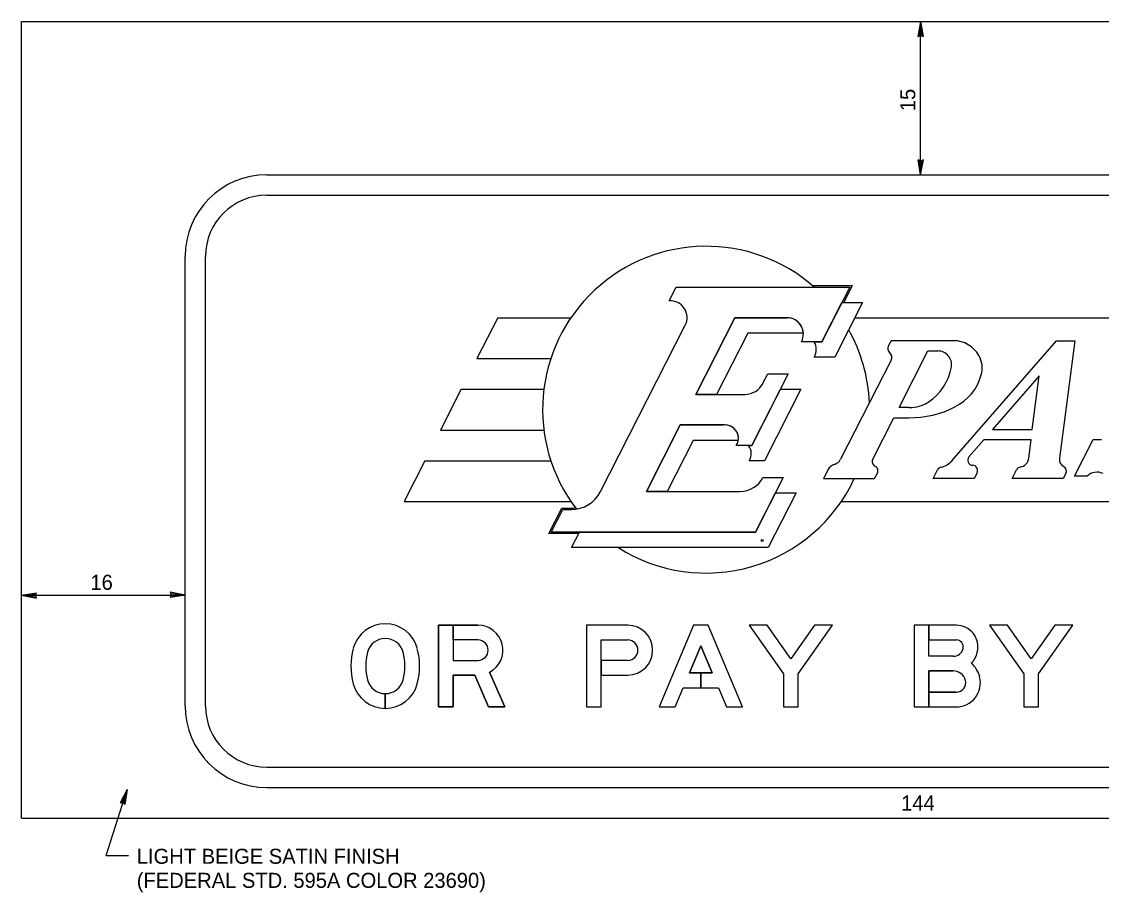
# Model space of a CAD drawing. Extents: x 60714 to 61340, y 9359 to 9750.
# Drawn here: x 60766.6 to 60967.4, y 9588.1 to 9750.1 of the extents above; entities that cross this region are included whole.
import ezdxf

# ---------------------------------------------------------------- set-up
doc = ezdxf.new("R2010")
doc.units = 0
for name, color, linetype in [('1', 7, 'Continuous'), ('2', 7, 'Continuous'), ('52', 7, 'Continuous'), ('GSBWFill', 7, 'Continuous'), ('SignPanel', 7, 'Continuous')]:
    doc.layers.add(name, color=color, linetype=linetype)

msp = doc.modelspace()

# ---------------------------------------------------------------- linework, layer by layer
at = {"layer": '1'}
for p, q in [((60933.77, 9721.63), (60933.77, 9750.13)), ((60766.57, 9643.41), (60796.97, 9643.41)), ((60782.32, 9595), (60786.23, 9607.24)), ((60782.32, 9595), (60786.43, 9594.97))]:
    msp.add_line(p, q, dxfattribs=at)
msp.add_circle((60904.31, 9653.58), 0.19, dxfattribs=at)
at = {"layer": '2'}
for p, q in [((60766.57, 9601.93), (60766.57, 9750.13)), ((60766.57, 9750.13), (61100.97, 9750.13)), ((60766.57, 9601.93), (61100.97, 9601.93))]:
    msp.add_line(p, q, dxfattribs=at)
at = {"layer": '52'}
for p, q in [((60933.77, 9750.13), (60933.23, 9747.37)), ((60933.77, 9750.13), (60933.49, 9747.48)), ((60933.77, 9750.13), (60934.21, 9747.35)), ((60933.77, 9750.13), (60933.96, 9747.47)), ((60933.23, 9747.37), (60933.73, 9747.57)), ((60933.73, 9747.57), (60934.21, 9747.35)), ((60933.77, 9721.63), (60933.33, 9724.41)), ((60933.81, 9724.19), (60933.33, 9724.41)), ((60933.77, 9721.63), (60933.58, 9724.29)), ((60933.77, 9721.63), (60934.31, 9724.39)), ((60933.77, 9721.63), (60934.05, 9724.28)), ((60934.31, 9724.39), (60933.81, 9724.19)), ((60766.57, 9643.41), (60769.35, 9643.85)), ((60766.57, 9643.41), (60769.23, 9643.6)), ((60766.57, 9643.41), (60769.33, 9642.88)), ((60766.57, 9643.41), (60769.22, 9643.13)), ((60769.13, 9643.37), (60769.35, 9643.85)), ((60769.33, 9642.88), (60769.13, 9643.37)), ((60794.41, 9643.46), (60794.19, 9642.97)), ((60796.97, 9643.41), (60794.19, 9642.97)), ((60796.97, 9643.41), (60794.21, 9643.95)), ((60794.21, 9643.95), (60794.41, 9643.46)), ((60796.97, 9643.41), (60794.31, 9643.69)), ((60796.97, 9643.41), (60794.31, 9643.23)), ((60786.23, 9607.24), (60784.88, 9604.78)), ((60786.23, 9607.24), (60785.15, 9604.8)), ((60786.23, 9607.24), (60785.59, 9604.65)), ((60786.23, 9607.24), (60785.8, 9604.46)), ((60784.88, 9604.78), (60785.41, 9604.82)), ((60785.41, 9604.82), (60785.8, 9604.46))]:
    msp.add_line(p, q, dxfattribs=at)
at = {"layer": 'GSBWFill'}
for p, q in [((60874.35, 9635.09), (60879.29, 9635.09)), ((60874.35, 9635.09), (60879.29, 9635.09)), ((60874.35, 9635.09), (60879.29, 9635.09)), ((60874.35, 9628.56), (60879.29, 9628.56)), ((60834.21, 9622.36), (60834.21, 9625.1)), ((60834.21, 9625.1), (60834.21, 9622.36)), ((60834.21, 9622.36), (60834.21, 9625.1)), ((60834.21, 9625.1), (60834.21, 9622.36)), ((60932.58, 9622.63), (60940.4, 9622.63))]:
    msp.add_line(p, q, dxfattribs=at)
for points in [[(60851.44, 9637.83), (60844.09, 9637.83), (60844.09, 9622.63), (60846.83, 9622.63), (60846.83, 9628.56), (60850.86, 9628.56), (60853.42, 9622.63), (60856.41, 9622.63), (60853.61, 9629.09)], [(60853.61, 9629.09), (60856.41, 9622.63), (60853.42, 9622.63), (60850.86, 9628.56), (60846.83, 9628.56), (60846.83, 9622.63), (60844.09, 9622.63), (60844.09, 9637.83), (60846.83, 9637.83), (60846.83, 9631.29), (60851.44, 9631.29)], [(60853.61, 9629.09), (60856.41, 9622.63), (60853.42, 9622.63), (60850.86, 9628.56), (60846.83, 9628.56), (60846.83, 9622.63), (60844.09, 9622.63), (60844.09, 9637.83), (60846.83, 9637.83), (60846.83, 9631.29), (60851.44, 9631.29)], [(60846.83, 9635.09), (60846.83, 9637.83), (60851.44, 9637.83)], [(60846.83, 9635.09), (60846.83, 9637.83), (60851.44, 9637.83)], [(60879.29, 9637.83), (60871.61, 9637.83), (60871.61, 9622.63), (60874.35, 9622.63), (60874.35, 9628.56)], [(60879.29, 9637.83), (60871.61, 9637.83), (60871.61, 9622.63), (60874.35, 9622.63), (60874.35, 9635.09)], [(60879.29, 9637.83), (60871.61, 9637.83), (60871.61, 9622.63), (60874.35, 9622.63), (60874.35, 9635.09)], [(60940.4, 9637.83), (60932.58, 9637.83), (60932.58, 9622.63)], [(60939.82, 9632.05), (60935.31, 9632.05), (60935.31, 9637.83), (60932.58, 9637.83), (60932.58, 9622.63), (60935.31, 9622.63)], [(60939.82, 9632.05), (60935.31, 9632.05), (60935.31, 9637.83), (60932.58, 9637.83), (60932.58, 9622.63), (60935.31, 9622.63)], [(60940.4, 9637.83), (60935.31, 9637.83), (60935.31, 9635.09), (60940.4, 9635.09)], [(60940.4, 9637.83), (60935.31, 9637.83), (60935.31, 9635.09), (60940.4, 9635.09)], [(60851.44, 9635.09), (60846.83, 9635.09), (60846.83, 9631.29), (60851.44, 9631.29)], [(60851.44, 9635.09), (60846.83, 9635.09)], [(60851.44, 9635.09), (60846.83, 9635.09)], [(60879.29, 9631.29), (60874.35, 9631.29), (60874.35, 9635.09)], [(60939.82, 9632.05), (60935.31, 9632.05), (60935.31, 9635.09), (60940.4, 9635.09)], [(60879.29, 9631.29), (60874.35, 9631.29), (60874.35, 9628.56), (60879.29, 9628.56)], [(60879.29, 9631.29), (60874.35, 9631.29), (60874.35, 9628.56), (60879.29, 9628.56)], [(60939.82, 9629.32), (60935.31, 9629.32), (60935.31, 9625.36), (60940.4, 9625.36)], [(60935.31, 9622.63), (60935.31, 9629.32), (60939.82, 9629.32)], [(60935.31, 9622.63), (60935.31, 9629.32), (60939.82, 9629.32)], [(60940.4, 9625.36), (60935.31, 9625.36), (60935.31, 9622.63), (60940.4, 9622.63)], [(60940.4, 9625.36), (60935.31, 9625.36), (60935.31, 9622.63), (60940.4, 9622.63)]]:
    msp.add_lwpolyline(points, dxfattribs=at)
for points in [[(60889.61, 9626.2), (60896.18, 9626.2), (60897.68, 9622.63), (60900.65, 9622.63), (60894.26, 9637.83), (60891.53, 9637.83), (60885.14, 9622.63), (60888.11, 9622.63)], [(60895.03, 9628.94), (60892.89, 9628.94), (60892.89, 9626.2), (60896.18, 9626.2), (60897.68, 9622.63), (60900.65, 9622.63), (60894.26, 9637.83), (60891.53, 9637.83), (60885.14, 9622.63), (60888.11, 9622.63), (60889.61, 9626.2), (60892.89, 9626.2), (60892.89, 9628.94), (60890.76, 9628.94), (60892.89, 9634.02)], [(60895.03, 9628.94), (60892.89, 9628.94), (60892.89, 9626.2), (60896.18, 9626.2), (60897.68, 9622.63), (60900.65, 9622.63), (60894.26, 9637.83), (60891.53, 9637.83), (60885.14, 9622.63), (60888.11, 9622.63), (60889.61, 9626.2), (60892.89, 9626.2), (60892.89, 9628.94), (60890.76, 9628.94), (60892.89, 9634.02)], [(60910.99, 9628.78), (60917.37, 9637.83), (60914.02, 9637.83), (60909.62, 9631.59), (60905.21, 9637.83), (60901.86, 9637.83), (60908.25, 9628.78), (60908.25, 9622.63), (60910.99, 9622.63)], [(60910.99, 9628.78), (60917.37, 9637.83), (60914.02, 9637.83), (60909.62, 9631.59), (60905.21, 9637.83), (60901.86, 9637.83), (60908.25, 9628.78), (60908.25, 9622.63), (60910.99, 9622.63)], [(60910.99, 9628.78), (60917.37, 9637.83), (60914.02, 9637.83), (60909.62, 9631.59), (60905.21, 9637.83), (60901.86, 9637.83), (60908.25, 9628.78), (60908.25, 9622.63), (60910.99, 9622.63)], [(60955.68, 9628.78), (60962.07, 9637.83), (60958.72, 9637.83), (60954.32, 9631.59), (60949.91, 9637.83), (60946.56, 9637.83), (60952.95, 9628.78), (60952.95, 9622.63), (60955.68, 9622.63)], [(60955.68, 9628.78), (60962.07, 9637.83), (60958.72, 9637.83), (60954.32, 9631.59), (60949.91, 9637.83), (60946.56, 9637.83), (60952.95, 9628.78), (60952.95, 9622.63), (60955.68, 9622.63)], [(60955.68, 9628.78), (60962.07, 9637.83), (60958.72, 9637.83), (60954.32, 9631.59), (60949.91, 9637.83), (60946.56, 9637.83), (60952.95, 9628.78), (60952.95, 9622.63), (60955.68, 9622.63)], [(60895.03, 9628.94), (60892.89, 9634.02), (60890.76, 9628.94)]]:
    msp.add_lwpolyline(points, close=True, dxfattribs=at)
for centre, radius, start, end in [((60834.21, 9631.94), 6.16, 14.9618, 165.0382), ((60834.21, 9631.94), 6.16, 14.9618, 165.0382), ((60834.21, 9631.94), 6.16, 14.9618, 165.0382), ((60851.44, 9633.19), 4.64, 297.837, 90), ((60851.44, 9633.19), 4.64, 297.837, 90), ((60851.44, 9633.19), 4.64, 297.837, 90), ((60940.4, 9633.8), 4.03, 345.5225, 90), ((60940.4, 9633.8), 4.03, 345.5225, 90), ((60940.4, 9633.8), 4.03, 345.5225, 90), ((60834.21, 9631.94), 3.42, 14.9618, 165.0382), ((60834.21, 9631.94), 3.42, 14.9618, 165.0382), ((60834.21, 9631.94), 3.42, 14.9618, 165.0382), ((60840.59, 9630.23), 12.77, 165.0382, 194.9618), ((60840.59, 9630.23), 12.77, 165.0382, 194.9618), ((60840.59, 9630.23), 12.77, 165.0382, 194.9618), ((60827.82, 9630.23), 12.77, 345.0382, 14.9618), ((60827.82, 9630.23), 12.77, 345.0382, 14.9618), ((60827.82, 9630.23), 12.77, 345.0382, 14.9618), ((60851.44, 9633.19), 1.9, 270, 90), ((60851.44, 9633.19), 1.9, 270, 90), ((60851.44, 9633.19), 1.9, 270, 90), ((60939.82, 9633.95), 1.9, 270, 345.5225), ((60939.82, 9633.95), 1.9, 270, 345.5225), ((60939.82, 9633.95), 1.9, 270, 345.5225), ((60940.4, 9633.8), 1.29, 345.5225, 90), ((60940.4, 9633.8), 1.29, 345.5225, 90), ((60940.4, 9633.8), 1.29, 345.5225, 90), ((60840.59, 9630.23), 10.03, 165.0382, 194.9618), ((60840.59, 9630.23), 10.03, 165.0382, 194.9618), ((60840.59, 9630.23), 10.03, 165.0382, 194.9618), ((60827.82, 9630.23), 10.03, 345.0382, 14.9618), ((60827.82, 9630.23), 10.03, 345.0382, 14.9618), ((60827.82, 9630.23), 10.03, 345.0382, 14.9618), ((60939.82, 9633.95), 4.64, 316.7114, 345.5225), ((60939.82, 9633.95), 4.64, 316.7114, 345.5225), ((60939.82, 9633.95), 4.64, 316.7114, 345.5225), ((60939.82, 9626.96), 2.36, 14.4775, 90), ((60939.82, 9626.96), 2.36, 14.4775, 90), ((60939.82, 9626.96), 2.36, 14.4775, 90), ((60939.82, 9626.96), 5.09, 14.4775, 48.4921), ((60939.82, 9626.96), 5.09, 14.4775, 48.4921), ((60939.82, 9626.96), 5.09, 14.4775, 48.4921), ((60834.21, 9628.52), 3.42, 194.9618, 345.0382), ((60834.21, 9628.52), 3.42, 194.9618, 270), ((60834.21, 9628.52), 3.42, 194.9618, 270), ((60834.21, 9628.52), 3.42, 270.0127, 345.0382), ((60834.21, 9628.52), 3.42, 270.0127, 345.0382), ((60940.4, 9627.11), 4.49, 270, 14.4775), ((60940.4, 9627.11), 4.49, 270, 14.4775), ((60940.4, 9627.11), 4.49, 270, 14.4775), ((60940.4, 9627.11), 1.75, 270, 14.4775), ((60940.4, 9627.11), 1.75, 270, 14.4775), ((60940.4, 9627.11), 1.75, 270, 14.4775), ((60834.21, 9628.52), 6.16, 194.9618, 345.0382), ((60834.21, 9628.52), 6.16, 194.9618, 270), ((60834.21, 9628.52), 6.16, 194.9618, 270), ((60834.21, 9628.52), 6.16, 270.0071, 345.0382), ((60834.21, 9628.52), 6.16, 270.0071, 345.0382)]:
    msp.add_arc(centre, radius, start, end, dxfattribs=at)
for major_axis in [(0, 4.64), (0, 4.64), (0, 4.64), (0, 1.9), (0, 1.9), (0, 1.9)]:
    msp.add_ellipse((60879.29, 9633.19), major_axis=major_axis, ratio=0.999994, start_param=3.141593, end_param=6.283185, dxfattribs=at)
at = {"layer": 'SignPanel'}
for p, q in [((60812.17, 9721.63), (61055.37, 9721.63)), ((60812.17, 9717.83), (61055.37, 9717.83)), ((60796.97, 9622.83), (60796.97, 9706.43)), ((60800.77, 9622.83), (60800.77, 9706.43)), ((60886.99, 9698.18), (60888.29, 9700.73)), ((60888.29, 9700.73), (60920.59, 9700.73)), ((60913.65, 9701.02), (60921.05, 9701.02)), ((60920.59, 9700.73), (60915.42, 9690.57)), ((60921.05, 9701.02), (60919.46, 9697.88)), ((60915.41, 9690.56), (60919.14, 9697.88)), ((60915.41, 9690.56), (60919.14, 9697.88)), ((60922.98, 9697.88), (60917.8, 9687.72)), ((60922.98, 9697.88), (60917.8, 9687.72)), ((60919.14, 9697.88), (60922.98, 9697.88)), ((60919.14, 9697.88), (60922.98, 9697.88)), ((60855.11, 9695.03), (60851.24, 9687.43)), ((60855.11, 9695.03), (60868.73, 9695.03)), ((60874.23, 9662.68), (60890, 9693.63)), ((60899.24, 9695.03), (60891.98, 9680.78)), ((60891.98, 9680.78), (60899.24, 9695.03)), ((60891.98, 9680.78), (60899.24, 9695.03)), ((60908.92, 9695.03), (60899.24, 9695.03)), ((60899.24, 9695.03), (60908.92, 9695.03)), ((60899.24, 9695.03), (60908.92, 9695.03)), ((60921.52, 9695.03), (61029.91, 9695.03)), ((60901.62, 9692.18), (60895.81, 9680.78)), ((60901.62, 9692.18), (60895.81, 9680.78)), ((60911.96, 9692.18), (60901.62, 9692.18)), ((60911.96, 9692.18), (60901.62, 9692.18)), ((60915.42, 9690.57), (60911.61, 9690.57)), ((60914, 9690.56), (60915.41, 9690.56)), ((60914, 9690.56), (60915.41, 9690.56)), ((60928.26, 9690.76), (60927.74, 9689.74)), ((60939.89, 9690.76), (60928.26, 9690.76)), ((60939.6, 9668.44), (60959.01, 9690.76)), ((60959.01, 9690.76), (60962.43, 9690.76)), ((60962.43, 9690.76), (60959.58, 9668.89)), ((60917.8, 9687.72), (60914, 9687.72)), ((60917.8, 9687.72), (60914, 9687.72)), ((60929.75, 9678.31), (60935.13, 9688.86)), ((60935.13, 9688.86), (60936.96, 9688.86)), ((60851.24, 9687.43), (60864.99, 9687.43)), ((60928.29, 9687.16), (60918.88, 9668.7)), ((60909.13, 9684.58), (60902.36, 9671.28)), ((60904.45, 9682.86), (60905.33, 9684.58)), ((60905.33, 9684.58), (60909.13, 9684.58)), ((60955.82, 9684.2), (60947.15, 9674.22)), ((60954.53, 9674.22), (60955.82, 9684.2)), ((60848.34, 9681.73), (60844.47, 9674.13)), ((60848.34, 9681.73), (60863.71, 9681.73)), ((60902.36, 9671.28), (60907.68, 9681.73)), ((60902.36, 9671.28), (60907.68, 9681.73)), ((60911.52, 9681.73), (60904.74, 9668.43)), ((60911.52, 9681.73), (60904.74, 9668.43)), ((60907.68, 9681.73), (60911.52, 9681.73)), ((60907.68, 9681.73), (60911.52, 9681.73)), ((60891.98, 9680.78), (60901.07, 9680.78)), ((60895.81, 9680.78), (60891.98, 9680.78)), ((60895.81, 9680.78), (60891.98, 9680.78)), ((60931.63, 9678.31), (60929.75, 9678.31)), ((60924.85, 9668.7), (60928.78, 9676.41)), ((60928.78, 9676.41), (60931.63, 9676.41)), ((60844.47, 9674.13), (60863.71, 9674.13)), ((60889.07, 9675.08), (60882.78, 9662.73)), ((60882.78, 9662.73), (60889.07, 9675.08)), ((60882.78, 9662.73), (60889.07, 9675.08)), ((60897.41, 9675.08), (60889.07, 9675.08)), ((60889.07, 9675.08), (60897.05, 9675.06)), ((60889.07, 9675.08), (60897.05, 9675.06)), ((60947.15, 9674.22), (60954.53, 9674.22)), ((60891.46, 9672.22), (60886.62, 9662.73)), ((60891.46, 9672.22), (60886.62, 9662.73)), ((60899.85, 9672.2), (60891.46, 9672.22)), ((60899.85, 9672.2), (60891.46, 9672.22)), ((60945.5, 9672.32), (60942.75, 9669.16)), ((60954.33, 9672.32), (60945.5, 9672.32)), ((60953.88, 9668.89), (60954.33, 9672.32)), ((60962.41, 9665.58), (60965.86, 9672.35)), ((60965.86, 9672.35), (60967.39, 9672.35)), ((60902.36, 9671.28), (60899.49, 9671.28)), ((60901.76, 9671.28), (60902.36, 9671.28)), ((60901.76, 9671.28), (60902.36, 9671.28)), ((60841.57, 9668.43), (60837.7, 9660.83)), ((60841.57, 9668.43), (60864.99, 9668.43)), ((60904.74, 9668.43), (60901.89, 9668.43)), ((60904.74, 9668.43), (60901.89, 9668.43)), ((60916.57, 9666.78), (60915.72, 9665.1)), ((60925.22, 9665.1), (60925.74, 9666.12)), ((60936.11, 9665.1), (60936.93, 9666.73)), ((60944.27, 9666.2), (60943.71, 9665.1)), ((60950.77, 9665.1), (60951.61, 9666.76)), ((60960.77, 9666.08), (60960.27, 9665.1)), ((60964.72, 9665.58), (60962.41, 9665.58)), ((60908.23, 9665.29), (60903.06, 9655.13)), ((60904.43, 9665.29), (60908.23, 9665.29)), ((60915.72, 9665.1), (60925.22, 9665.1)), ((60943.71, 9665.1), (60936.11, 9665.1)), ((60960.27, 9665.1), (60950.77, 9665.1)), ((60882.78, 9662.73), (60900.22, 9662.73)), ((60886.62, 9662.73), (60882.78, 9662.73)), ((60886.62, 9662.73), (60882.78, 9662.73)), ((60903.06, 9655.13), (60906.78, 9662.44)), ((60903.06, 9655.13), (60906.78, 9662.44)), ((60910.62, 9662.44), (60905.44, 9652.28)), ((60910.62, 9662.44), (60905.44, 9652.28)), ((60906.78, 9662.44), (60910.62, 9662.44)), ((60906.78, 9662.44), (60910.62, 9662.44)), ((60837.7, 9660.83), (60868.73, 9660.83)), ((60864.65, 9654.88), (60867.06, 9659.61)), ((60867.06, 9659.61), (60868.81, 9659.61)), ((60919, 9660.83), (61012.48, 9660.83)), ((60865.06, 9655.13), (60867.21, 9659.36)), ((60867.21, 9659.36), (60868.81, 9659.36)), ((60870.18, 9654.88), (60864.65, 9654.88)), ((60903.06, 9655.13), (60865.06, 9655.13)), ((60868.86, 9652.28), (60870.31, 9655.13)), ((60868.86, 9652.28), (60870.31, 9655.13)), ((60870.31, 9655.13), (60903.06, 9655.13)), ((60870.31, 9655.13), (60903.06, 9655.13)), ((60905.44, 9652.28), (60868.86, 9652.28)), ((60905.44, 9652.28), (60868.86, 9652.28)), ((60812.17, 9611.43), (61055.37, 9611.43)), ((60812.17, 9607.63), (61055.37, 9607.63))]:
    msp.add_line(p, q, dxfattribs=at)
for centre, radius, start, end in [((60812.17, 9706.43), 15.2, 90, 180), ((60812.17, 9706.43), 11.4, 90, 180), ((60893.87, 9677.93), 30.4, 48.5904, 217.4727), ((60887.2, 9695.05), 3.14, 332.9998, 93.8045), ((60908.92, 9691.99), 3.04, 332.2089, 90), ((60908.92, 9691.99), 3.04, 3.5833, 90), ((60908.92, 9691.99), 3.04, 3.5833, 90), ((60893.87, 9677.93), 30.4, 2.4236, 29.2771), ((60911.31, 9689.14), 3.04, 332.2089, 27.9127), ((60911.31, 9689.14), 3.04, 332.2089, 27.9127), ((60928.59, 9689.31), 0.95, 152.9784, 231.1602), ((60939.89, 9685.34), 5.42, 29.4315, 90), ((60927.28, 9687.68), 1.14, 333.0027, 51.1602), ((60936.95, 9686.29), 2.57, 351.076, 90), ((60940.47, 9685.66), 4.75, 344.7074, 29.4315), ((60930.1, 9687.36), 9.5, 302.4206, 351.076), ((60935.89, 9686.92), 9.5, 296.6432, 344.7074), ((60901.07, 9684.58), 3.8, 270, 332.9883), ((60931.63, 9684.96), 6.65, 270, 302.4206), ((60931.63, 9695.41), 19, 270, 296.6432), ((60897.41, 9672.61), 2.47, 350.3502, 98.3344), ((60897.41, 9672.61), 2.47, 350.3502, 98.3344), ((60897.41, 9672.61), 2.47, 327.421, 90), ((60899.81, 9669.76), 2.47, 327.421, 37.9799), ((60899.81, 9669.76), 2.47, 327.421, 37.9799), ((60918.27, 9665.92), 1.9, 106.4317, 152.9742), ((60917.19, 9669.56), 1.9, 286.4317, 332.9959), ((60925.7, 9668.27), 0.95, 152.9884, 244.7832), ((60924.89, 9666.55), 0.95, 333.0239, 64.7832), ((60936.74, 9670.93), 3.8, 282.7162, 318.9966), ((60943.47, 9668.53), 0.95, 138.9824, 268.6869), ((60943.42, 9666.63), 0.95, 332.9784, 88.6869), ((60952, 9669.13), 1.9, 279.2397, 352.5632), ((60961.09, 9668.69), 1.52, 172.5884, 241.8673), ((60937.78, 9666.3), 0.95, 102.7162, 153.0239), ((60952.46, 9666.32), 0.95, 99.2397, 153.0239), ((60959.92, 9666.51), 0.95, 332.9784, 61.8673), ((60966.54, 9663.64), 2.66, 64.3795, 133.1892), ((60893.87, 9677.93), 30.4, 237.5383, 335.047), ((60900.22, 9667.48), 4.75, 270, 332.5096), ((60868.81, 9665.44), 6.08, 270, 332.9991), ((60868.81, 9665.44), 5.83, 270, 277.5038), ((60812.17, 9622.83), 15.2, 180, 270), ((60812.17, 9622.83), 11.4, 180, 270)]:
    msp.add_arc(centre, radius, start, end, dxfattribs=at)

# ---------------------------------------------------------------- texts
at = {"layer": '1'}
for s, rotation, p in [('15', 90, (60932.77, 9733.46)), ('16', 0, (60779.37, 9644.41)), ('144', 0, (60930.14, 9603.35)), ('LIGHT BEIGE SATIN FINISH', 0, (60787.99, 9593.44)), ('(FEDERAL STD. 595A COLOR 23690)', 0, (60787.99, 9588.96))]:
    msp.add_text(s, height=2.8, rotation=rotation, dxfattribs=at).set_placement(p)

doc.saveas('drawing.dxf')
